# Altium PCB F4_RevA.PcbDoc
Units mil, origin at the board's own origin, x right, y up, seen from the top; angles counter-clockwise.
Board outline 1377.95 x 1181.1 mil, 2 copper layers (Top Layer, Bottom Layer); 19 components, 89 nets, 138 pads, 68 vias.
Unrouted connection lines stored in the file: 21.
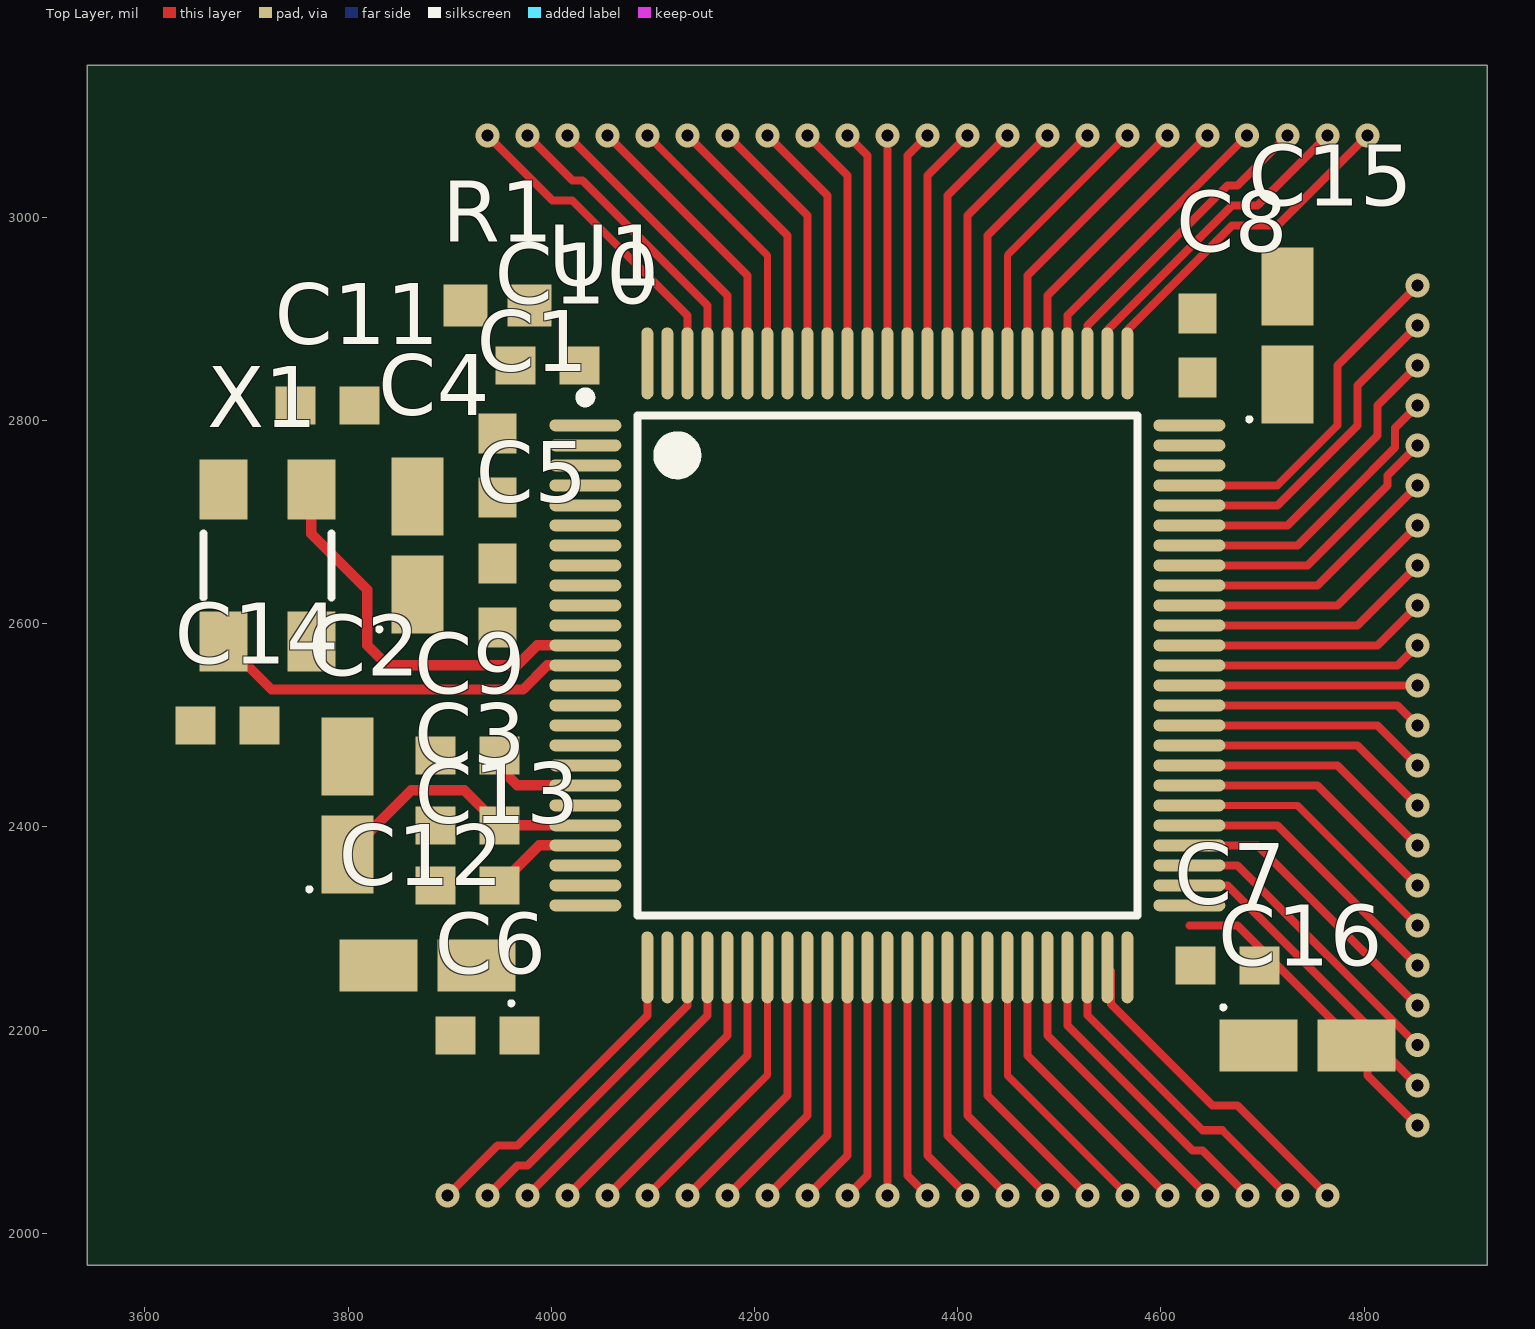
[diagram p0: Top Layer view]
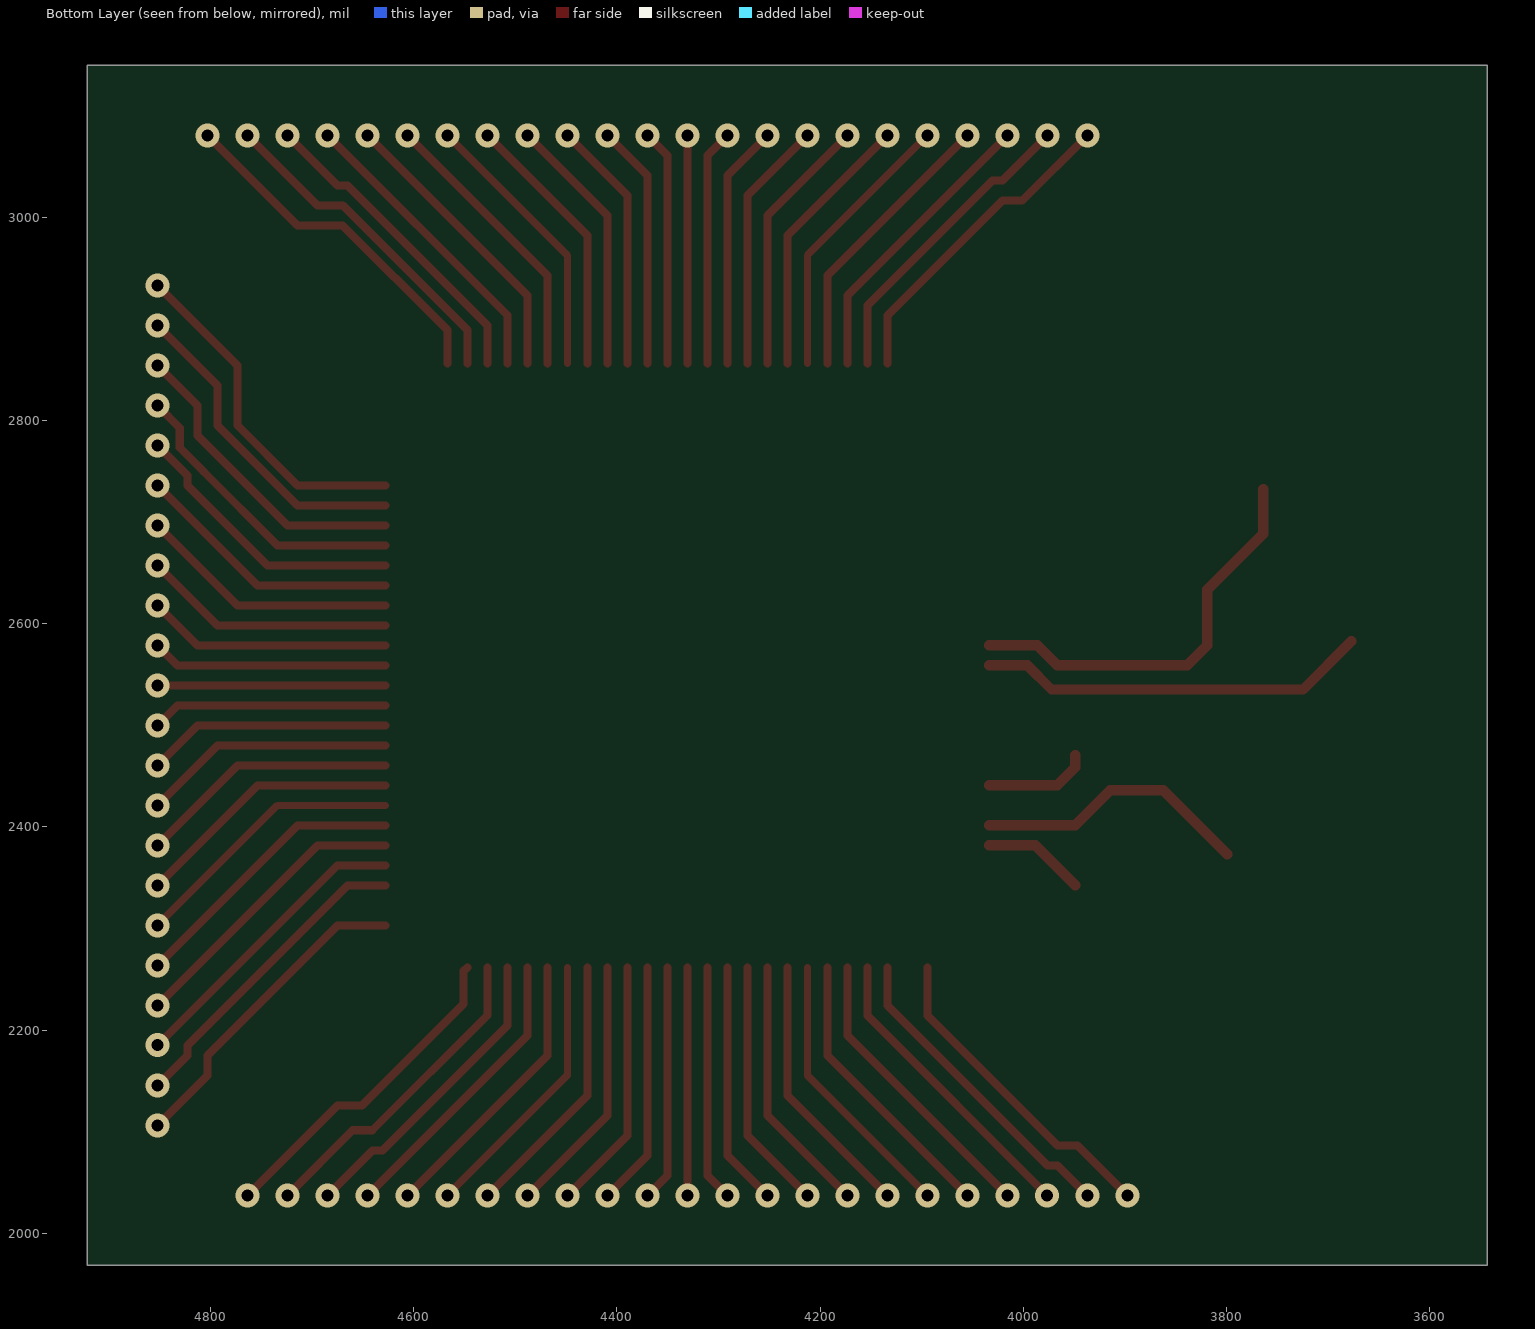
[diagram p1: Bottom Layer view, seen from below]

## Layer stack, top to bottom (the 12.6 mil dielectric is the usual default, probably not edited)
Top Solder: solder mask 0.4, Solder Resist, Dk 3.5
Top Layer: signal copper 1.4
Dielectric 1: dielectric 12.6, FR-4, Dk 4.8
Bottom Layer: signal copper 1.4
Bottom Solder: solder mask 0.4, Solder Resist, Dk 3.5

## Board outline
3543.31,3149.61 4921.26,3149.61 4921.26,1968.5 3543.31,1968.5 3543.31,3149.61

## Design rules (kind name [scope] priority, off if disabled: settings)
Clearance [All] p1: gap=6
MinimumSolderMaskSliver [All] p1: minsoldermaskwidth=4
PolygonConnect [All] p1: connectstyle=Relief reliefconductorwidth=10 reliefentries=4 polygonreliefangle="90 Angle" airgapwidth=10
RoutingVias [All] p1: holewidth=28 width=50 viastyle="Through Hole" minholewidth=28 minwidth=50 maxholewidth=28 maxwidth=50
SolderMaskExpansion [All] p1: expansion=2
Width [All] p1: maxlimit=100 minlimit=6 preferedwidth=10
28 further rules are at their usual default settings.

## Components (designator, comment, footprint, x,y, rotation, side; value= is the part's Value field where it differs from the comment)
C1 "Capacitor" C0603 3946.85,2755.91 r90 top
C2 "Polarized Capacitor" TCAXM8R 3799.21,2421.26 r90 top
C3 "Capacitor" C0603 3917.32,2401.57 r0 top
C4 "Polarized Capacitor" TCAXM8R 3868.11,2677.17 r90 top
C5 "Capacitor" C0603 3946.85,2627.95 r270 top
C6 "Capacitor" C0603 3937.01,2194.88 r180 top
C7 "Capacitor" C0603 4665.35,2263.78 r180 top
C8 "Capacitor" C0603 4635.83,2874.02 r270 top
C9 "Capacitor" C0603 3917.32,2470.47 r180 top
C10 "Capacitor" C0603 3996.06,2854.33 r180 top
C11 "Capacitor" C0603 3779.53,2814.96 r0 top
C12 "Polarized Capacitor" TCAXM8R 3877.95,2263.78 r180 top
C13 "Capacitor" C0603 3917.32,2342.52 r0 top
C14 "Capacitor" C0603 3681.1,2500 r0 top
C15 "Polarized Capacitor" TCAXM8R 4724.41,2883.86 r90 top
C16 "Polarized Capacitor" TCAXM8R 4744.09,2185.04 r0 top
R1 "Resistor" ERA3A 3946.85,2913.39 r180 top
U1 "STM32F407" STM-LQFP100_N 4330.71,2559.06 r0 top
X1 "CTS-405X" 405XO 3720.47,2657.48 r90 top

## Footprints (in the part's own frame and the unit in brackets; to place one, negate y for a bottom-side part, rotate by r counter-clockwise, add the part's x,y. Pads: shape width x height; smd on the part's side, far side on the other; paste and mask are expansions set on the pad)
405XO [mm] "CTS 405 Series Crystal Oscillator"
  rect 1.5x1.2 smd: 1(-1.9,1.1) 2(1.9,1.1) 3(1.9,-1.1) 4(-1.9,-1.1)
  silkscreen extent -0.8,-1.6 0.8,1.6
C0603 [mm] "Kemet C0603 Ceramic Capacitor"
  rect 1x0.95 smd: 1(-0.8,0) 2(0.8,0)
  body extent -0.88,-0.48 0.87,0.48, height 0.87
ERA3A [mm] "ERA3A Panasonic Thin Film Resistor 0603"
  rect 1.1x1.05 smd: 1(-0.8,0) 2(0.8,0)
  body extent -0.9,-0.5 0.9,0.5, height 0.55
STM-LQFP100_N [mm] "Thin QFP, 100-Leads, Body 14x14mm, Pitch 0.5mm, IPC Medium Density"
  oval 1.8x0.3 smd: 1(-7.55,6) 2(-7.55,5.5) 3(-7.55,5) 4(-7.55,4.5) 5(-7.55,4) 6(-7.55,3.5) 7(-7.55,3) 8(-7.55,2.5) 9(-7.55,2) 10(-7.55,1.5) 11(-7.55,1) 12(-7.55,0.5) 13(-7.55,0) 14(-7.55,-0.5) 15(-7.55,-1) 16(-7.55,-1.5) 17(-7.55,-2) 18(-7.55,-2.5) 19(-7.55,-3) 20(-7.55,-3.5) 21(-7.55,-4) 22(-7.55,-4.5) 23(-7.55,-5) 24(-7.55,-5.5) 25(-7.55,-6) 51(7.55,-6) 52(7.55,-5.5) 53(7.55,-5) 54(7.55,-4.5) 55(7.55,-4) 56(7.55,-3.5) 57(7.55,-3) 58(7.55,-2.5) 59(7.55,-2) 60(7.55,-1.5) 61(7.55,-1) 62(7.55,-0.5) 63(7.55,0) 64(7.55,0.5) 65(7.55,1) 66(7.55,1.5) 67(7.55,2) 68(7.55,2.5) 69(7.55,3) 70(7.55,3.5) 71(7.55,4) 72(7.55,4.5) 73(7.55,5) 74(7.55,5.5) 75(7.55,6)
  oval 0.3x1.8 smd: 26(-6,-7.55) 27(-5.5,-7.55) 28(-5,-7.55) 29(-4.5,-7.55) 30(-4,-7.55) 31(-3.5,-7.55) 32(-3,-7.55) 33(-2.5,-7.55) 34(-2,-7.55) 35(-1.5,-7.55) 36(-1,-7.55) 37(-0.5,-7.55) 38(0,-7.55) 39(0.5,-7.55) 40(1,-7.55) 41(1.5,-7.55) 42(2,-7.55) 43(2.5,-7.55) 44(3,-7.55) 45(3.5,-7.55) 46(4,-7.55) 47(4.5,-7.55) 48(5,-7.55) 49(5.5,-7.55) 50(6,-7.55) 76(6,7.55) 77(5.5,7.55) 78(5,7.55) 79(4.5,7.55) 80(4,7.55) 81(3.5,7.55) 82(3,7.55) 83(2.5,7.55) 84(2,7.55) 85(1.5,7.55) 86(1,7.55) 87(0.5,7.55) 88(0,7.55) 89(-0.5,7.55) 90(-1,7.55) 91(-1.5,7.55) 92(-2,7.55) 93(-2.5,7.55) 94(-3,7.55) 95(-3.5,7.55) 96(-4,7.55) 97(-4.5,7.55) 98(-5,7.55) 99(-5.5,7.55) 100(-6,7.55)
  silkscreen extent -7.67,-6.25 6.25,6.82, body extent -7,-7 7,7, height 1.6
TCAXM8R [mm] "TCA Tantalum Capacitor 1206 Rohm"
  rect 1.95x1.3 smd: 1(-1.225,0) 2(1.225,0)
  silkscreen extent -2.15,0.9 -2.05,1, body extent -1.7,-0.9 1.7,0.9, height 1.8

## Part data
C1 C3 C5 C6 C7 C8 C9 C10 C11 C13 C14: library part CAP, "Capacitor Non Polarized"
C2 C4 C12 C15 C16: library part CAP_POL, "Polarized Capacitor - Tantalum"
R1: library part RES
U1: "STM32F407 32 bit Microcontroller"
X1: library part CTS-405, "CTS 405 Series Crystal Oscillator"

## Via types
v1: diameter 23.62, hole 11.81, Top Layer to Bottom Layer, 68 vias

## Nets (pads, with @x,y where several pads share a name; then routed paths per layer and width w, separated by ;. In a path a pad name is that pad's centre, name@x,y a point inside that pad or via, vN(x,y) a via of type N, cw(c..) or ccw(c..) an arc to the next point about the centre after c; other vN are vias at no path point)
3V: C2.1 C3.2 C4.1 C5.2 C6.2 C7.2 C8.2 C9.1 C10.1 C12.1 C13.2 R1.2 U1.11 U1.19 U1.21 U1.22 U1.28 U1.50 U1.75 U1.100 | length 791.1
  Top Layer w8: v1(3937.01,2037.4) 3966.54,2066.93 3976.38,2066.93 4133.86,2224.41 U1.28
  Top Layer w10: C2.1 3862.2,2436.02 3914.37,2436.02 C3.2 U1.21 ; C13.2 3988.19,2381.89 U1.22 ; C9.1 3948.82,2458.66 3966.54,2440.94 U1.19
BATT: C1.1 U1.6
BOOT0: R1.1 U1.94 | length 273.3
  Top Layer w7: v1(4094.49,3080.71) 4212.6,2962.6 U1.94
GND: C1.2 C2.2 C3.1 C4.2 C5.1 C6.1 C7.1 C8.1 C9.2 C10.2 C11.2 C12.2 C13.1 C14.2 C15.2 C16.2 U1.10 U1.20 U1.27 U1.74 U1.99 | length 317.5
  Top Layer w8: 4627.95,2303.15 4675.2,2303.15 4803.15,2175.2 4803.15,2155.51 v1(4852.36,2106.3)
NetC11_1: C11.1 U1.12 X1.3 | length 407.2
  Top Layer w10: X1.3 3763.78,2688.63 3818.9,2633.51 3818.9,2578.74 3838.58,2559.06 3966.54,2559.06 3986.22,2578.74 U1.12
NetC14_1: C14.1 U1.13 X1.1 | length 385.8
  Top Layer w10: X1.1 3724.63,2535.21 3972.22,2535.21 3996.06,2559.06 U1.13
NetC15_1: C15.1 U1.73
NetC16_1: C16.1 U1.49 | length 328.4
  Top Layer w8: U1.49 4551.02,2258.03 4551.02,2225.7 4650.73,2125.98 4675.2,2125.98 v1(4763.78,2037.4)
NRST: U1.14
PA0: U1.23
PA1: U1.24
PA2: U1.25
PA3: U1.26 | length 317.5
  Top Layer w8: v1(3897.64,2037.4) 3946.85,2086.61 3966.54,2086.61 4094.49,2214.57 U1.26
PA4: U1.29 | length 297.9
  Top Layer w8: v1@3976.38,2037.4 v1(3976.49,2037.4) 4153.54,2214.45 U1.29
PA5: U1.30 | length 289.6
  Top Layer w8: v1(4015.75,2037.4) 4173.23,2194.88 U1.30
PA6: U1.31 | length 281.5
  Top Layer w8: v1(4055.12,2037.4) 4192.91,2175.2 U1.31
PA7: U1.32 | length 273.3
  Top Layer w7: v1(4094.49,2037.4) 4212.6,2155.51 U1.32
PA8: U1.67 | length 265.2
  Top Layer w8: U1.67 4753.94,2637.8 v1(4852.36,2736.22)
PA9: U1.68 | length 279.1
  Top Layer w8: U1.68 4744.09,2657.48 4822.83,2736.22 4822.83,2746.06 v1(4852.36,2775.59)
PA10: U1.69 | length 293
  Top Layer w8: U1.69 4734.25,2677.17 4807.18,2750.09 4807.18,2750.21 4830.33,2773.36 4830.33,2792.7 4852.36,2814.73 v1(4852.36,2814.96)
PA11: U1.70 | length 306.9
  Top Layer w8: U1.70 4724.41,2696.85 4812.99,2785.43 4812.99,2814.96 v1(4852.36,2854.33)
PA12: U1.71 | length 320.9
  Top Layer w8: U1.71 4714.57,2716.54 4793.31,2795.28 4793.31,2834.65 v1(4852.36,2893.7)
PA13: U1.72 | length 340.5
  Top Layer w8: U1.72 4714.45,2736.22 4773.62,2795.39 4773.62,2854.33 v1(4852.36,2933.07)
PA14: U1.76 | length 348.4
  Top Layer w8: U1.76 4566.93,2889.14 4669.91,2992.13 4714.57,2992.13 v1(4803.15,3080.71)
PA15: U1.77 | length 328.8
  Top Layer w8: U1.77 4547.24,2889.26 4669.8,3011.81 4694.88,3011.81 v1(4763.78,3080.71)
PB0: U1.35 | length 248.9
  Top Layer w8: v1(4212.6,2037.4) 4271.65,2096.46 U1.35
PB1: U1.36 | length 240.7
  Top Layer w8: v1(4251.97,2037.4) 4291.34,2076.77 U1.36
PB2: U1.37 | length 232.6
  Top Layer w8: v1(4291.34,2037.4) 4311.02,2057.09 U1.37
PB3: U1.89 | length 232.6
  Top Layer w8: v1(4291.34,3080.71) 4311.02,3061.02 U1.89
PB4: U1.90 | length 240.7
  Top Layer w8: v1(4251.97,3080.71) 4291.34,3041.34 U1.90
PB5: U1.91 | length 248.9
  Top Layer w8: v1(4212.6,3080.71) 4271.65,3021.65 U1.91
PB6: U1.92 | length 257
  Top Layer w8: v1(4173.23,3080.71) 4251.97,3001.97 U1.92
PB7: U1.93 | length 265.2
  Top Layer w8: v1(4133.86,3080.71) 4232.28,2982.28 U1.93
PB8: U1.95 | length 281.5
  Top Layer w8: v1(4055.12,3080.71) 4192.91,2942.91 U1.95
PB9: U1.96 | length 289.6
  Top Layer w8: v1(4015.75,3080.71) 4173.23,2923.23 U1.96
PB10: U1.47 | length 303.6
  Top Layer w8: U1.47 4507.87,2204.72 4630.91,2081.69 4640.75,2081.69 v1(4685.04,2037.4)
PB11: U1.48 | length 317.4
  Top Layer w8: U1.48 4527.56,2214.68 4640.81,2101.43 4660.38,2101.43 v1(4724.41,2037.4)
PB12: U1.51
PB13: U1.52 | length 311.7
  Top Layer w8: U1.52 4665.35,2342.52 4822.83,2185.04 4822.83,2175.2 v1(4852.36,2145.67)
PB14: U1.53 | length 297.9
  Top Layer w8: U1.53 4675.31,2362.2 v1(4852.36,2185.15) v1@4852.36,2185.04
PB15: U1.54 | length 289.6
  Top Layer w8: U1.54 4694.88,2381.89 v1(4852.36,2224.41)
PC0: U1.15
PC1: U1.16
PC2: U1.17
PC3: U1.18
PC4: U1.33 | length 265.2
  Top Layer w8: v1(4133.86,2037.4) 4232.28,2135.83 U1.33
PC5: U1.34 | length 257
  Top Layer w8: v1(4173.23,2037.4) 4251.97,2116.14 U1.34
PC6: U1.63 | length 232.6
  Top Layer w8: U1.63 4832.68,2559.05 v1(4852.36,2578.74)
PC7: U1.64 | length 240.7
  Top Layer w8: U1.64 4812.99,2578.74 v1(4852.36,2618.11)
PC8: U1.65 | length 248.9
  Top Layer w8: U1.65 4793.31,2598.43 v1(4852.36,2657.48)
PC9: U1.66 | length 257
  Top Layer w8: U1.66 4773.62,2618.11 v1(4852.36,2696.85)
PC10: U1.78 | length 311.7
  Top Layer w8: U1.78 4527.56,2893.7 4665.35,3031.5 4675.2,3031.5 v1(4724.41,3080.71)
PC11: U1.79 | length 297.9
  Top Layer w8: U1.79 4507.87,2903.66 v1(4684.93,3080.71) v1@4685.04,3080.71
PC12: U1.80 | length 289.6
  Top Layer w8: U1.80 4488.19,2923.23 v1(4645.67,3080.71)
PC13: U1.7
PC14: U1.8
PC15: U1.9
PD0: U1.81 | length 281.5
  Top Layer w8: U1.81 4468.5,2942.91 v1(4606.3,3080.71)
PD1: U1.82 | length 273.3
  Top Layer w7: U1.82 4448.82,2962.6 v1(4566.93,3080.71)
PD2: U1.83 | length 265.2
  Top Layer w8: U1.83 4429.13,2982.28 v1(4527.56,3080.71)
PD3: U1.84 | length 257
  Top Layer w8: U1.84 4409.45,3001.97 v1(4488.19,3080.71)
PD4: U1.85 | length 248.9
  Top Layer w8: U1.85 4389.76,3021.65 v1(4448.82,3080.71)
PD5: U1.86 | length 240.7
  Top Layer w8: U1.86 4370.08,3041.34 v1(4409.45,3080.71)
PD6: U1.87 | length 232.6
  Top Layer w8: U1.87 4350.39,3061.02 v1(4370.08,3080.71)
PD7: U1.88 | length 224.4
  Top Layer w8: U1.88 v1(4330.71,3080.71)
PD8: U1.55 | length 281.5
  Top Layer w8: U1.55 4714.57,2401.57 v1(4852.36,2263.78)
PD9: U1.56 | length 273.3
  Top Layer w7: U1.56 4734.25,2421.26 v1(4852.36,2303.15)
PD10: U1.57 | length 265.2
  Top Layer w8: U1.57 4753.94,2440.94 v1(4852.36,2342.52)
PD11: U1.58 | length 257
  Top Layer w8: U1.58 4773.62,2460.63 v1(4852.36,2381.89)
PD12: U1.59 | length 248.9
  Top Layer w8: U1.59 4793.31,2480.32 v1(4852.36,2421.26)
PD13: U1.60 | length 240.7
  Top Layer w8: U1.60 4812.99,2500 v1(4852.36,2460.63)
PD14: U1.61 | length 232.6
  Top Layer w8: U1.61 4832.68,2519.69 v1(4852.36,2500)
PD15: U1.62 | length 224.4
  Top Layer w8: U1.62 v1(4852.36,2539.37)
PE0: U1.97 | length 303.6
  Top Layer w8: v1(3976.38,3080.71) 4020.67,3036.42 4030.51,3036.42 4153.54,2913.39 U1.97
PE1: U1.98 | length 317.4
  Top Layer w8: v1(3937.01,3080.71) 4001.04,3016.68 4020.61,3016.68 4133.86,2903.43 U1.98
PE2: U1.1
PE3: U1.2
PE4: U1.3
PE5: U1.4
PE6: U1.5
PE7: U1.38 | length 224.4
  Top Layer w8: v1(4330.71,2037.4) U1.38
PE8: U1.39 | length 232.6
  Top Layer w8: U1.39 4350.39,2057.09 v1(4370.08,2037.4)
PE9: U1.40 | length 240.7
  Top Layer w8: U1.40 4370.08,2076.77 v1(4409.45,2037.4)
PE10: U1.41 | length 248.9
  Top Layer w8: U1.41 4389.76,2096.46 v1(4448.82,2037.4)
PE11: U1.42 | length 257
  Top Layer w8: U1.42 4409.45,2116.14 v1(4488.19,2037.4)
PE12: U1.43 | length 265.2
  Top Layer w8: U1.43 4429.13,2135.83 v1(4527.56,2037.4)
PE13: U1.44 | length 273.3
  Top Layer w7: U1.44 4448.82,2155.51 v1(4566.93,2037.4)
PE14: U1.45 | length 281.5
  Top Layer w8: U1.45 4468.5,2175.2 v1(4606.3,2037.4)
PE15: U1.46 | length 289.6
  Top Layer w8: U1.46 4488.19,2194.88 v1(4645.67,2037.4)
pads on no net: X1.2 X1.4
